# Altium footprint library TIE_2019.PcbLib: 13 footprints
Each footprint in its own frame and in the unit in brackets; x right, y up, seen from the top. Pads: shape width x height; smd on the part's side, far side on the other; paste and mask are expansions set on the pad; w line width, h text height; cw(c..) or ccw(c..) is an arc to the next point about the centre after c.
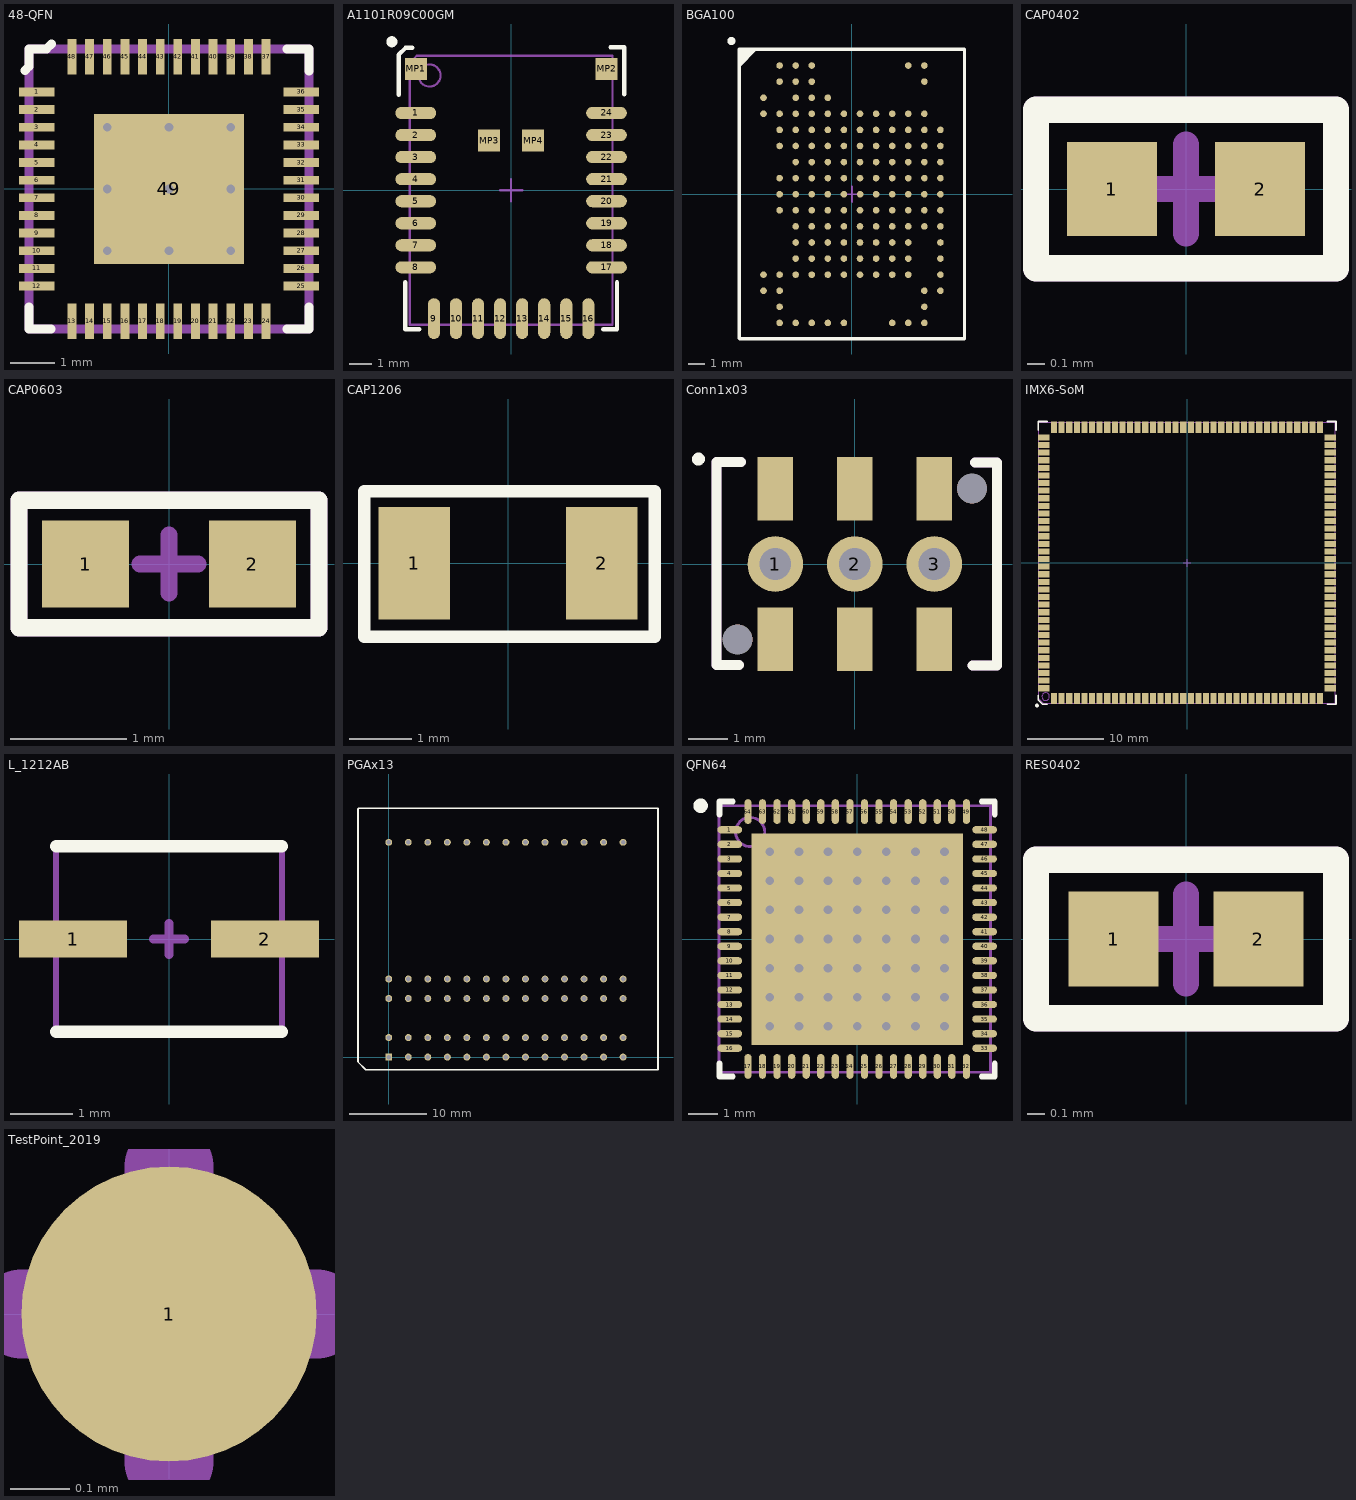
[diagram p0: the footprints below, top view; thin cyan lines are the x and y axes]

## 48-QFN [mm] "6x6mm QFN Package"
pads (49):
  rect 0.8x0.2 smd mask+0.05: 1(-3,2.2) 2(-3,1.8) 3(-3,1.4) 4(-3,1) 5(-3,0.6) 6(-3,0.2) 7(-3,-0.2) 8(-3,-0.6) 9(-3,-1) 10(-3,-1.4) 11(-3,-1.8) 12(-3,-2.2) 25(3,-2.2) 26(3,-1.8) 27(3,-1.4) 28(3,-1) 29(3,-0.6) 30(3,-0.2) 31(3,0.2) 32(3,0.6) 33(3,1) 34(3,1.4) 35(3,1.8) 36(3,2.2)
  rect 0.2x0.8 smd mask+0.05: 13(-2.2,-3) 14(-1.8,-3) 15(-1.4,-3) 16(-1,-3) 17(-0.6,-3) 18(-0.2,-3) 19(0.2,-3) 20(0.6,-3) 21(1,-3) 22(1.4,-3) 23(1.8,-3) 24(2.2,-3) 37(2.2,3) 38(1.8,3) 39(1.4,3) 40(1,3) 41(0.6,3) 42(0.2,3) 43(-0.2,3) 44(-0.6,3) 45(-1,3) 46(-1.4,3) 47(-1.8,3) 48(-2.2,3)
  rect 3.4x3.4 smd paste-10 mask+0.05: 49(0,0)
via 0,0 diameter 0.4 hole 0.2
via -1.4,1.4 diameter 0.4 hole 0.2
via 0,1.4 diameter 0.4 hole 0.2
via 1.4,1.4 diameter 0.4 hole 0.2
via 1.4,0 diameter 0.4 hole 0.2
via -1.4,0 diameter 0.4 hole 0.2
via -1.4,-1.4 diameter 0.4 hole 0.2
via 0,-1.4 diameter 0.4 hole 0.2
via 1.4,-1.4 diameter 0.4 hole 0.2
Top Overlay:
  lines w0.2: -3.261,2.69 -3.175,2.776 -3.175,3.175 -2.776,3.175 -2.661,3.29 ; -3.175,-2.675 -3.175,-3.175 -2.675,-3.175 ; 2.675,-3.175 3.175,-3.175 3.175,-2.675 ; 2.675,3.175 3.175,3.175 3.175,2.675
Top Paste:
  region: 1.55,-0.15 0.15,-0.15 0.15,-1.55 1.55,-1.55
  region: 1.55,1.55 0.15,1.55 0.15,0.15 1.55,0.15
  rectangle: -1.55,0.15 -0.15,1.55
  rectangle: -1.55,-1.55 -0.15,-0.15
Top Assembly:
  text ".Designator" at -2.5,-0.155 h0.5
Mechanical 10:
  lines w0.2: -3.175,-3.175 3.175,-3.175 3.175,3.175 -3.175,3.175 -3.175,-3.175
Mechanical 1(UNUSED):
  lines w0.15: -0.25,0 0.25,0 ; 0,-0.25 0,0.25
3D body "VSC8531XMW-01.stp": height 0.9, standoff 0, extent -3.05,-3.05 3.05,3.05

## A1101R09C00GM [mm] "Sub-GHz Modules 900MHz Radio Only Connector"
height 2.1
pads (28):
  oval 1.85x0.55 smd: 1(-4.325,3.5) 2(-4.325,2.5) 3(-4.325,1.5) 4(-4.325,0.5) 5(-4.325,-0.5) 6(-4.325,-1.5) 7(-4.325,-2.5) 8(-4.325,-3.5) 17(4.325,-3.5) 18(4.325,-2.5) 19(4.325,-1.5) 20(4.325,-0.5) 21(4.325,0.5) 22(4.325,1.5) 23(4.325,2.5) 24(4.325,3.5)
  oval 0.55x1.85 smd: 9(-3.5,-5.825) 10(-2.5,-5.825) 11(-1.5,-5.825) 12(-0.5,-5.825) 13(0.5,-5.825) 14(1.5,-5.825) 15(2.5,-5.825) 16(3.5,-5.825)
  rect 1x1 smd: MP1(-4.325,5.5) MP2(4.325,5.5) MP3(-1,2.25) MP4(1,2.25)
Top Overlay:
  circle w0.25: c-5.41,6.731 r0.125
  lines w0.2: -5.105,4.327 -5.105,6.14 -4.792,6.452 -4.48,6.452 ; -4.8,-4.175 -4.8,-6.3 -4.175,-6.3 ; 4.175,-6.3 4.8,-6.3 4.8,-4.175 ; 4.505,6.478 5.13,6.478 5.13,4.353
Top Component Center:
  lines w0.1: -0.5,0 0.5,0 ; 0,-0.5 0,0.5
Top Assembly:
  circle w0.1: c-3.7,5.2 r0.5
  lines w0.1: -4.6,-6.1 -4.6,5.787 -4.287,6.1 4.6,6.1 4.6,-6.1 -4.6,-6.1
  text ".Designator" at -2.5,-0.155 h0.5
3D body: height 2.1, standoff 0, extent -4.6,-6.1 4.6,6.1

## BGA100 [mm] "BGA, 100-Leads, Body 14.00x18.00mmx1.40mm, Pitch 1.00mm"
height 1.4
pads (142):
  round 0.41 smd: A1(-4.5,8) A2(-3.5,8) A3(-2.5,8) A9(3.5,8) A10(4.5,8) B1(-4.5,7) B2(-3.5,7) B3(-2.5,7) B10(4.5,7) C0(-5.5,6) C2(-3.5,6) C3(-2.5,6) C4(-1.5,6) D0(-5.5,5) D1(-4.5,5) D2(-3.5,5) D3(-2.5,5) D4(-1.5,5) D5(-0.5,5) D6(0.5,5) D7(1.5,5) D8(2.5,5) D9(3.5,5) D10(4.5,5) E1(-4.5,4) E2(-3.5,4) E3(-2.5,4) E4(-1.5,4) E5(-0.5,4) E6(0.5,4) E7(1.5,4) E8(2.5,4) E9(3.5,4) E10(4.5,4) E11(5.5,4) F1(-4.5,3) F2(-3.5,3) F3(-2.5,3) F4(-1.5,3) F5(-0.5,3) F6(0.5,3) F7(1.5,3) F8(2.5,3) F9(3.5,3) F10(4.5,3) F11(5.5,3) G2(-3.5,2) G3(-2.5,2) G4(-1.5,2) G5(-0.5,2) G6(0.5,2) G7(1.5,2) G8(2.5,2) G9(3.5,2) G10(4.5,2) G11(5.5,2) H1(-4.5,1) H2(-3.5,1) H3(-2.5,1) H4(-1.5,1) H5(-0.5,1) H6(0.5,1) H7(1.5,1) H8(2.5,1) H9(3.5,1) H10(4.5,1) H11(5.5,1) J1(-4.5,0) J2(-3.5,0) J3(-2.5,0) J4(-1.5,0) J5(-0.5,0) J6(0.508,0) J7(1.5,0) J8(2.5,0) J9(3.5,0) J10(4.5,0) J11(5.5,0) K1(-4.5,-1) K2(-3.5,-1) K3(-2.5,-1) K4(-1.5,-1) K5(-0.5,-1) K6(0.5,-1) K7(1.5,-1) K8(2.5,-1) K9(3.5,-1) K10(4.5,-1) K11(5.5,-1) L2(-3.5,-2) L3(-2.5,-2) L4(-1.5,-2) L5(-0.5,-2) L6(0.5,-2) L7(1.5,-2) L8(2.5,-2) L9(3.5,-2) L10(4.5,-2) L11(5.5,-2) M2(-3.5,-3) M3(-2.5,-3) M4(-1.5,-3) M5(-0.5,-3) M6(0.5,-3) M7(1.5,-3) M8(2.5,-3) M9(3.5,-3) M11(5.5,-3) N2(-3.5,-4) N3(-2.5,-4) N4(-1.5,-4) N5(-0.5,-4) N6(0.5,-4) N7(1.5,-4) N8(2.5,-4) N9(3.5,-4) N11(5.5,-4) P0(-5.5,-5) P1(-4.5,-5) P2(-3.5,-5) P3(-2.5,-5) P4(-1.5,-5) P5(-0.5,-5) P6(0.5,-5) P7(1.5,-5) P8(2.5,-5) P9(3.5,-5) P11(5.5,-5) R0(-5.5,-6) R1(-4.5,-6) R10(4.5,-6) R11(5.5,-6) T1(-4.5,-7) T10(4.5,-7) U1(-4.5,-8) U2(-3.5,-8) U3(-2.5,-8) U4(-1.5,-8) U5(-0.5,-8) U8(2.5,-8) U9(3.5,-8) U10(4.5,-8)
Top Overlay:
  circle w0.25: c-7.493,9.525 r0.125
  region: -6,9 -7,8 -7,9
  lines w0.2: -7,8 -6,9 ; -7.007,-8.971 -7.007,9.029 6.993,9.029 6.993,-8.971 -7.007,-8.971 ; -7,-9 -7,9 7,9 7,-9 -7,-9
Top Component Center:
  lines w0.1: -0.5,0 0.5,0 ; 0,-0.5 0,0.5
Top Assembly:
  lines w0.1: -7,-9 -7,9 7,9 7,-9 -7,-9
  text ".Designator" at -2.474,-0.13 h0.5
3D body: height 1.4, standoff 0.25, extent -7,-9 7,9

## CAP0402 [mm]
pads (2):
  rect 0.51x0.535 smd mask+0.05: 1(-0.42,0) 2(0.42,0)
Top Overlay:
  lines w0.15: -0.85,-0.45 0.85,-0.45 0.85,0.45 -0.85,0.45 -0.85,-0.45
Top Component Center:
  lines w0.15: -0.25,0 0.25,0 ; 0,-0.25 0,0.25
Top Assembly:
  lines w0.15: -0.85,-0.45 0.85,-0.45 0.85,0.45 -0.85,0.45 -0.85,-0.45
  text ".Designator" at -0.569,-0.257 h0.5
3D body "Ceramic_Capacitor_0402_h20mil.step": height 0.51, standoff 0, extent -0.508,-0.254 0.508,0.254

## CAP0603 [mm]
pads (2):
  rect 0.75x0.75 smd mask+0.05: 1(-0.72,0) 2(0.72,0)
Top Overlay:
  lines w0.15: -1.295,-0.55 -1.295,0.55 1.295,0.55 1.295,-0.55 -1.295,-0.55
Top Component Center:
  lines w0.15: -0.25,0 0.25,0 ; 0,-0.25 0,0.25
Top Assembly:
  lines w0.15: -1.295,-0.55 1.295,-0.55 1.295,0.55 -1.295,0.55 -1.295,-0.55
3D body "Ceramic_Capacitor_0603_h32mil.step": height 0.8, standoff 0, extent -0.8,-0.4 0.8,0.4

## CAP1206 [mm]
pads (2):
  rect 1.15x1.8 smd: 1(-1.5,0) 2(1.5,0)
Top Overlay:
  lines w0.2: -2.3,-1.175 2.35,-1.175 2.35,1.15 -2.3,1.15 -2.3,-1.175
3D body "C1206C104K5RALTU.stp": height 0.88, standoff 0, extent -1.7,-0.9 1.7,0.9

## Conn1x03 [mm]
pads (11):
  round 1.4 hole 0.8: 1(-2,0) 2(0,0) 3(2,0)
  round 0.75 hole 0.75 mask-0.5: ""(-2.95,-1.9) ""(2.95,1.9)
  rect 0.9x1.6 smd mask+0.05: ""(-2,-1.9) ""(-2,1.9) ""(0,-1.9) ""(0,1.9) ""(2,-1.9) ""(2,1.9)
Top Overlay:
  circle w0.254: c-3.937,2.642 r0.036
  lines w0.254: -3.48,-2.54 -2.921,-2.54 -3.48,-2.54 ; -3.48,-2.54 -3.48,2.565 ; -3.48,-2.54 -3.48,2.565 ; -3.48,2.565 -2.87,2.565 -3.48,2.565 ; 3.581,-2.553 3.581,2.553 ; 3.581,-2.553 2.972,-2.553 3.581,-2.553 ; 3.581,-2.553 3.581,2.553 ; 3.581,2.553 3.023,2.553 3.581,2.553
Top Assembly:
  lines w0.254: -2.921,-2.54 -3.48,-2.54 -3.48,2.565 -2.87,2.565 ; 3.581,-2.553 2.972,-2.553 3.581,-2.553 ; 3.581,-2.553 3.581,2.553 ; 3.581,-2.553 3.581,2.553 ; 3.581,2.553 3.023,2.553 3.581,2.553
3D body "c-2315312-1-b-3d.stp": height 5.2, standoff -1.9, extent -3.25,-2.4 3.25,2.4

## IMX6-SoM [mm]
height 3
pads (140):
  rect 0.8x1.5 smd: 1(-17.5,-17.85) 2(-16.5,-17.85) 3(-15.5,-17.85) 4(-14.5,-17.85) 5(-13.5,-17.85) 6(-12.5,-17.85) 7(-11.5,-17.85) 8(-10.5,-17.85) 9(-9.5,-17.85) 10(-8.5,-17.85) 11(-7.5,-17.85) 12(-6.5,-17.85) 13(-5.5,-17.85) 14(-4.5,-17.85) 15(-3.5,-17.85) 16(-2.5,-17.85) 17(-1.5,-17.85) 18(-0.5,-17.85) 19(0.5,-17.85) 20(1.5,-17.85) 21(2.5,-17.85) 22(3.5,-17.85) 23(4.5,-17.85) 24(5.5,-17.85) 25(6.5,-17.85) 26(7.5,-17.85) 27(8.5,-17.85) 28(9.5,-17.85) 29(10.5,-17.85) 30(11.5,-17.85) 31(12.5,-17.85) 32(13.5,-17.85) 33(14.5,-17.85) 34(15.5,-17.85) 35(16.5,-17.85) 36(17.5,-17.85) 71(17.5,17.85) 72(16.5,17.85) 73(15.5,17.85) 74(14.5,17.85) 75(13.5,17.85) 76(12.5,17.85) 77(11.5,17.85) 78(10.5,17.85) 79(9.5,17.85) 80(8.5,17.85) 81(7.5,17.85) 82(6.5,17.85) 83(5.5,17.85) 84(4.5,17.85) 85(3.5,17.85) 86(2.5,17.85) 87(1.5,17.85) 88(0.5,17.85) 89(-0.5,17.85) 90(-1.5,17.85) 91(-2.5,17.85) 92(-3.5,17.85) 93(-4.5,17.85) 94(-5.5,17.85) 95(-6.5,17.85) 96(-7.5,17.85) 97(-8.5,17.85) 98(-9.5,17.85) 99(-10.5,17.85) 100(-11.5,17.85) 101(-12.5,17.85) 102(-13.5,17.85) 103(-14.5,17.85) 104(-15.5,17.85) 105(-16.5,17.85) 106(-17.5,17.85)
  rect 1.5x0.8 smd: 37(18.85,-16.5) 38(18.85,-15.5) 39(18.85,-14.5) 40(18.85,-13.5) 41(18.85,-12.5) 42(18.85,-11.5) 43(18.85,-10.5) 44(18.85,-9.5) 45(18.85,-8.5) 46(18.85,-7.5) 47(18.85,-6.5) 48(18.85,-5.5) 49(18.85,-4.5) 50(18.85,-3.5) 51(18.85,-2.5) 52(18.85,-1.5) 53(18.85,-0.5) 54(18.85,0.5) 55(18.85,1.5) 56(18.85,2.5) 57(18.85,3.5) 58(18.85,4.5) 59(18.85,5.5) 60(18.85,6.5) 61(18.85,7.5) 62(18.85,8.5) 63(18.85,9.5) 64(18.85,10.5) 65(18.85,11.5) 66(18.85,12.5) 67(18.85,13.5) 68(18.85,14.5) 69(18.85,15.5) 70(18.85,16.5) 107(-18.85,16.5) 108(-18.85,15.5) 109(-18.85,14.5) 110(-18.85,13.5) 111(-18.85,12.5) 112(-18.85,11.5) 113(-18.85,10.5) 114(-18.85,9.5) 115(-18.85,8.5) 116(-18.85,7.5) 117(-18.85,6.5) 118(-18.85,5.5) 119(-18.85,4.5) 120(-18.85,3.5) 121(-18.85,2.5) 122(-18.85,1.5) 123(-18.85,0.5) 124(-18.85,-0.5) 125(-18.85,-1.5) 126(-18.85,-2.5) 127(-18.85,-3.5) 128(-18.85,-4.5) 129(-18.85,-5.5) 130(-18.85,-6.5) 131(-18.85,-7.5) 132(-18.85,-8.5) 133(-18.85,-9.5) 134(-18.85,-10.5) 135(-18.85,-11.5) 136(-18.85,-12.5) 137(-18.85,-13.5) 138(-18.85,-14.5) 139(-18.85,-15.5) 140(-18.85,-16.5)
Top Overlay:
  circle w0.25: c-19.75,-18.775 r0.125
  lines w0.2: -19.6,-17.425 -19.6,-18.012 -19.012,-18.6 -18.425,-18.6 ; -19.6,17.425 -19.6,18.6 -18.425,18.6 ; 18.425,-18.6 19.6,-18.6 19.6,-17.425 ; 18.425,18.6 19.6,18.6 19.6,17.425
Top Assembly:
  circle w0.1: c-18.6,-17.6 r0.5
  lines w0.1: -19.5,-17.912 -19.5,18.5 19.5,18.5 19.5,-18.5 -18.912,-18.5 -19.5,-17.912
Mechanical 15:
  lines w0.1: -0.5,0 0.5,0 ; 0,-0.5 0,0.5
3D body: height 3, standoff 0, extent -19.5,-18.5 19.5,18.5

## L_1212AB [mm]
pads (2):
  rect 1.75x0.6 smd: 1(-1.55,0) 2(1.55,0)
Top Overlay:
  lines w0.2: -1.825,-1.5 1.825,-1.5 ; -1.825,1.5 1.825,1.5
Top Component Center:
  lines w0.15: -0.25,0 0.25,0 ; 0,-0.25 0,0.25
Top Assembly:
  lines w0.1: -1.825,-1.5 -1.825,1.5 1.825,1.5 1.825,-1.5 -1.825,-1.5
3D body "IHLP1212ABEV1R0M01.stp": height 2, standoff 0, extent -1.825,-1.449 1.825,1.551

## PGAx13 [mm]
pads (65):
  rect 0.9x0.9 hole 0.6 mask+0.1: A1(0,0)
  round 0.9 hole 0.6 mask+0.1: A2(2.54,0) A3(5.08,0) A4(7.62,0) A5(10.16,0) A6(12.7,0) A7(15.24,0) A8(17.78,0) A9(20.32,0) A10(22.86,0) A11(25.4,0) A12(27.94,0) A13(30.48,0) B1(0,2.54) B2(2.54,2.54) B3(5.08,2.54) B4(7.62,2.54) B5(10.16,2.54) B6(12.7,2.54) B7(15.24,2.54) B8(17.78,2.54) B9(20.32,2.54) B10(22.86,2.54) B11(25.4,2.54) B12(27.94,2.54) B13(30.48,2.54) D1(0,7.62) D2(2.54,7.62) D3(5.08,7.62) D4(7.62,7.62) D5(10.16,7.62) D6(12.7,7.62) D7(15.24,7.62) D8(17.78,7.62) D9(20.32,7.62) D10(22.86,7.62) D11(25.4,7.62) D12(27.94,7.62) D13(30.48,7.62) E1(0,10.16) E2(2.54,10.16) E3(5.08,10.16) E4(7.62,10.16) E5(10.16,10.16) E6(12.7,10.16) E7(15.24,10.16) E8(17.78,10.16) E9(20.32,10.16) E10(22.86,10.16) E11(25.4,10.16) E12(27.94,10.16) E13(30.48,10.16) M1(0,27.94) M2(2.54,27.94) M3(5.08,27.94) M4(7.62,27.94) M5(10.16,27.94) M6(12.7,27.94) M7(15.24,27.94) M8(17.78,27.94) M9(20.32,27.94) M10(22.86,27.94) M11(25.4,27.94) M12(27.94,27.94) M13(30.48,27.94)
Top Overlay:
  lines w0.2: -4,32.3 -4,-0.623 -2.983,-1.64 35.02,-1.64 35.02,32.36 -3.98,32.36
Top Assembly:
  text ".Designator" at -2.5,-0.155 h0.5

## QFN64 [mm] "QFN, 64-Leads, Body 9.00x9.00mm, Pitch 0.50mm, Thermal Pad 7.25x7.25mm, IPC Medium Density"
height 0.8
pads (65):
  oval 0.85x0.25 smd mask+0.07: 1(-4.375,3.75) 2(-4.375,3.25) 3(-4.375,2.75) 4(-4.375,2.25) 5(-4.375,1.75) 6(-4.375,1.25) 7(-4.375,0.75) 8(-4.375,0.25) 9(-4.375,-0.25) 10(-4.375,-0.75) 11(-4.375,-1.25) 12(-4.375,-1.75) 13(-4.375,-2.25) 14(-4.375,-2.75) 15(-4.375,-3.25) 16(-4.375,-3.75) 33(4.375,-3.75) 34(4.375,-3.25) 35(4.375,-2.75) 36(4.375,-2.25) 37(4.375,-1.75) 38(4.375,-1.25) 39(4.375,-0.75) 40(4.375,-0.25) 41(4.375,0.25) 42(4.375,0.75) 43(4.375,1.25) 44(4.375,1.75) 45(4.375,2.25) 46(4.375,2.75) 47(4.375,3.25) 48(4.375,3.75)
  oval 0.25x0.85 smd mask+0.07: 17(-3.75,-4.375) 18(-3.25,-4.375) 19(-2.75,-4.375) 20(-2.25,-4.375) 21(-1.75,-4.375) 22(-1.25,-4.375) 23(-0.75,-4.375) 24(-0.25,-4.375) 25(0.25,-4.375) 26(0.75,-4.375) 27(1.25,-4.375) 28(1.75,-4.375) 29(2.25,-4.375) 30(2.75,-4.375) 31(3.25,-4.375) 32(3.75,-4.375) 49(3.75,4.375) 50(3.25,4.375) 51(2.75,4.375) 52(2.25,4.375) 53(1.75,4.375) 54(1.25,4.375) 55(0.75,4.375) 56(0.25,4.375) 57(-0.25,4.375) 58(-0.75,4.375) 59(-1.25,4.375) 60(-1.75,4.375) 61(-2.25,4.375) 62(-2.75,4.375) 63(-3.25,4.375) 64(-3.75,4.375)
  rect 7.25x7.25 smd paste+0 mask+0.07: ""(-0.001,-0.007)
via -1,-3 diameter 0.6 hole 0.3
via -2,-3 diameter 0.6 hole 0.3
via -3,-3 diameter 0.6 hole 0.3
via -1,-2 diameter 0.6 hole 0.3
via -2,-2 diameter 0.6 hole 0.3
via -3,-2 diameter 0.6 hole 0.3
via -3,-1 diameter 0.6 hole 0.3
via -2,-1 diameter 0.6 hole 0.3
via -1,-1 diameter 0.6 hole 0.3
via -3,0 diameter 0.6 hole 0.3
via -2,0 diameter 0.6 hole 0.3
via -1,0 diameter 0.6 hole 0.3
via -3,1 diameter 0.6 hole 0.3
via -2,1 diameter 0.6 hole 0.3
via -1,1 diameter 0.6 hole 0.3
via 3,1 diameter 0.6 hole 0.3
via 2,1 diameter 0.6 hole 0.3
via 1,1 diameter 0.6 hole 0.3
via 3,0 diameter 0.6 hole 0.3
via 2,0 diameter 0.6 hole 0.3
via 1,0 diameter 0.6 hole 0.3
via 3,-1 diameter 0.6 hole 0.3
via 2,-1 diameter 0.6 hole 0.3
via 1,-1 diameter 0.6 hole 0.3
via 3,-2 diameter 0.6 hole 0.3
via 2,-2 diameter 0.6 hole 0.3
via 1,-2 diameter 0.6 hole 0.3
via 3,-3 diameter 0.6 hole 0.3
via 2,-3 diameter 0.6 hole 0.3
via 1,-3 diameter 0.6 hole 0.3
via 0,-3 diameter 0.6 hole 0.3
via 0,-2 diameter 0.6 hole 0.3
via 0,-1 diameter 0.6 hole 0.3
via -3,3 diameter 0.6 hole 0.3
via -2,3 diameter 0.6 hole 0.3
via -1,3 diameter 0.6 hole 0.3
via -3,2 diameter 0.6 hole 0.3
via -2,2 diameter 0.6 hole 0.3
via -1,2 diameter 0.6 hole 0.3
via 3,2 diameter 0.6 hole 0.3
via 2,2 diameter 0.6 hole 0.3
via 1,2 diameter 0.6 hole 0.3
via 3,3 diameter 0.6 hole 0.3
via 2,3 diameter 0.6 hole 0.3
via 1,3 diameter 0.6 hole 0.3
via 0,3 diameter 0.6 hole 0.3
via 0,2 diameter 0.6 hole 0.3
via 0,1 diameter 0.6 hole 0.3
via 0,0 diameter 0.6 hole 0.3
Top Overlay:
  circle w0.25: c-5.375,4.575 r0.125
  lines w0.2: -4.725,-4.275 -4.725,-4.725 -4.275,-4.725 ; -4.725,4.275 -4.725,4.725 -4.275,4.725 ; 4.275,-4.725 4.725,-4.725 4.725,-4.275 ; 4.275,4.725 4.725,4.725 4.725,4.275
Top Assembly:
  circle w0.1: c-3.675,3.675 r0.5
  lines w0.1: -4.738,-4.575 -4.738,4.575 4.575,4.575 4.575,-4.575 -4.738,-4.575
  text ".Designator" at -2.5,-0.162 h0.5
3D body: height 0.8, standoff 0.08, extent -4.575,-4.575 4.575,4.575

## RES0402 [mm]
pads (2):
  rect 0.51x0.54 smd mask+0.05: 1(-0.41,0) 2(0.41,0)
Top Overlay:
  lines w0.15: -0.85,-0.45 0.85,-0.45 0.85,0.45 -0.85,0.45 -0.85,-0.45
Top Component Center:
  lines w0.15: -0.25,0 0.25,0 ; 0,-0.25 0,0.25
Top Assembly:
  lines w0.15: -0.85,-0.45 -0.85,0.45 0.85,0.45 0.85,-0.45 -0.85,-0.45
3D body "User Library-CR1005-0402.STEP": height 0.35, standoff 0, extent -0.5,-0.25 0.5,0.25

## TestPoint_2019 [mm]
pads (1):
  round 0.5 smd paste-10 mask+0.1: 1(0,0)
Mechanical 1(UNUSED):
  lines w0.15: -0.25,0 0.25,0 ; 0,-0.25 0,0.25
